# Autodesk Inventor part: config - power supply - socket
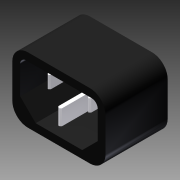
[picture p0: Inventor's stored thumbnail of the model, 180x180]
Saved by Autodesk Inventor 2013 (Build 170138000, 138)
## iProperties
Company: Autodesk Inc.
Created: 2005-12
Part Number: config - power supply - socket
Document SubType Name: Modeling
Designer: Autodesk Inc.
Stock Number: config - power supply - socket
Density: 1 g/cm^3
Mass: 6.75547 g
Surface Area: 46.2073 cm^2
Volume: 6.75547 cm^3
Material: Allgemein
Title: PC Demo
Author: Autodesk Inc.
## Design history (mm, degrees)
sketch "Sketch1"
  geometry: L1 (0, 4)-(0, -24) reference; L2 (-21, 0)-(21, 0) reference; L3 (-15, 0)-(15, 0); L4 (15, 0)-(15, -20); L5 (15, -20)-(-15, -20); L6 (-15, -20)-(-15, 0)
  constraints: 8 end point, 2 parallel, 1 horizontal, 1 perpendicular, 1 point on line, 1 other
  dimensions: "d0" = 30 distance of L4.end L5.end; "d1" = 20 distance of L5.end L3.start
extrude "Extrusion1" new body sketch "Sketch1" distance "d2" = 21; taper "d3" = 0 deg
fillet "Fillet1" dims "d4" = 5
sketch "Sketch2"
  geometry: L1 (20, 0)-(0, 0) reference; L2 (25, 5)-(25, 16) reference; L3 (20, 21)-(0, 21) reference; L4 (-5, 5)-(-5, 16) reference; L5 (-2.5, 18.5)-(22.5, 18.5); L6 (22.5, 18.5)-(22.5, 2.5); L7 (22.5, 2.5)-(-2.5, 2.5); L8 (-2.5, 2.5)-(-2.5, 18.5)
  constraints: 8 end point, 2 parallel, 1 horizontal, 1 perpendicular
  dimensions: "d5" = 2.5 distance between parallel lines of L5 L3; "d6" = 2.5 distance between parallel lines of L4 L8 (= d5); "d7" = 2.5 distance between parallel lines of L2 L6 (= d6); "d8" = 2.5 distance between parallel lines of L1 L7 (= d5)
extrude "Extrusion2" cut sketch "Sketch2" distance "d9" = 15; taper "d10" = 0 deg
fillet "Fillet2" dims "d11" = 2
chamfer "Chamfer1" distance "d12" = 5; stored, may be unused: second distance "d13" = 2, angle "d14" = 45 deg
sketch "Sketch3"
  geometry: L1 (20.5, 18.5)-(-0.5, 18.5) reference; L2 (2.5, 2.5)-(17.5, 2.5) reference; L3 (10, 25.2)-(10, -4.2) reference; L4 (-11, 0)-(31, 0) reference; L5 (3, 15)-(4, 15); L6 (4, 15)-(4, 11); L7 (4, 11)-(3, 11); L8 (3, 11)-(3, 15); L9 (9.4, 10.5)-(10.6, 10.5); L10 (10.6, 10.5)-(10.6, 5.5); L11 (10.6, 5.5)-(9.4, 5.5); L12 (9.4, 5.5)-(9.4, 10.5); L13 (16, 15)-(17, 15); L14 (17, 15)-(17, 11); L15 (17, 11)-(16, 11); L16 (16, 11)-(16, 15)
  constraints: 24 end point, 6 parallel, 3 horizontal, 3 perpendicular, 2 collinear, 3 other
  dimensions: "d15" = 4 distance of L7.end L5.start; "d16" = 3.5 distance between parallel lines of L1 L5; "d17" = 12 distance between parallel lines of L16 L6; "d18" = 1 distance of L6.end L7.end; "d19" = 1.2 distance of L10.end L11.end; "d20" = 5 distance of L9.end L10.end; "d21" = 3 distance between parallel lines of L2 L11
extrude "Extrusion3" join sketch "Sketch3" distance "d22" = 12; taper "d23" = 0 deg
extrude "Extrusion4" join sketch "Sketch3" distance "d24" = 15; taper "d25" = 0 deg
chamfer "Chamfer2" distance "d26" = 0.4; stored, may be unused: second distance "d27" = 2, angle "d28" = 45 deg
body "Solid1"
